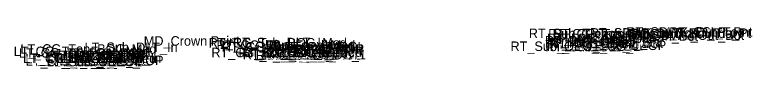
# Model space of a CAD drawing. Extents: x 0 to 6300, y 0 to 9528.
# Drawn here: x 2126 to 2203.7, y 9500.5 to 9504.9 of the extents above; entities that cross this region are included whole.
import ezdxf

# ---------------------------------------------------------------- set-up
doc = ezdxf.new("R2010")
doc.units = 0
doc.layers.add('Default', color=7, linetype='Continuous')

msp = doc.modelspace()

# ---------------------------------------------------------------- texts
at = {"layer": 'Default'}
for s, p in [('RT_Sub_Trench_Out_DLT', (2180.181, 9503.749)), ('RT_CG_Top_Face', (2182.225, 9503.709)), ('RT_CG_Top_BOC', (2182.694, 9503.709)), ('RT_SDWK_In_Top', (2186.62, 9503.799)), ('RT_SDWK_Out_Top', (2190.462, 9503.899)), ('RT_SDWK_Out_Bot', (2190.711, 9503.566)), ('Exterior Boundary', (2192.061, 9503.779)), ('RT_CSLP_Pnt', (2194.981, 9503.899)), ('RT_Tie_Pt', (2197.224, 9503.779)), ('MD_Crown Point', (2139.582, 9502.953)), ('RT_CG_Top_BOC_Med', (2146.431, 9502.753)), ('RT_Sub_DLT_In', (2148.978, 9502.795)), ('RT_PV2_OEOT', (2181.873, 9502.979)), ('RT_PV3_OEOT', (2181.873, 9502.729)), ('RT_PV1_OEOT', (2182.112, 9503.229)), ('RT_CG1_Shelf_Out', (2182.36, 9502.736)), ('RT_CG_Top_Gut', (2182.752, 9503.209)), ('RT_SDWK_In_Bot', (2186.869, 9503.466)), ('LT_CG_Top_BOC_Med', (2126.569, 9502.108)), ('LT_Sub_DLT_In', (2133.339, 9502.288)), ('RT_CG_Top_Face_Med', (2147.246, 9502.503)), ('RT_CG_Top_Gut_Med', (2147.8, 9502.337)), ('RT_PV2_OEEOP', (2152.167, 9502.109)), ('RT_PV2_IEEOP', (2152.928, 9502.109)), ('RT_PV2_PGL', (2154.145, 9502.109)), ('RT_PV1_PGL', (2154.385, 9502.359)), ('RT_Sub_OEOT_CG_1', (2178.247, 9502.396)), ('RT_Sub_OEOT', (2181.92, 9502.354)), ('RT_CG_Bot_IE', (2182.221, 9502.646)), ('RT_CG_Bot_BOC', (2182.97, 9502.721)), ('RT_Sub_OEOP', (2185.154, 9502.493)), ('LT_CG_Top_Face_Med', (2125.866, 9501.858)), ('LT_CG_Top_Gut_Med', (2126.418, 9501.692)), ('LT_CG_Bot_BOC_Med', (2126.846, 9501.131)), ('LT_PV2_OEEOP', (2129.285, 9501.419)), ('LT_PV3_OEEOP', (2129.285, 9501.169)), ('LT_PV2_IEEOP', (2130.046, 9501.419)), ('LT_CG1_Shelf_In', (2130.712, 9501.146)), ('LT_PV2_PGL', (2131.264, 9501.419)), ('LT_PV1_PGL', (2131.503, 9501.669)), ('RT_CG_Bot_BOC_Med', (2146.708, 9501.731)), ('RT_CG1_Shelf_In', (2149.573, 9501.716)), ('RT_CG_Bot_IE_Med', (2149.976, 9501.776)), ('RT_Sub_IEOT_CG_1', (2150.007, 9501.526)), ('RT_Sub_IEOP', (2151.404, 9501.458)), ('RT_PV3_OEEOP', (2152.167, 9501.859)), ('RT_Sub_OEEOP', (2152.214, 9501.484)), ('RT_Sub_IEEOP', (2152.975, 9501.484)), ('RT_Sub_PGL', (2154.192, 9501.484)), ('LT_CG_Bot_IE_Med', (2127.094, 9501.086)), ('LT_Sub_IEOT_CG_1', (2127.125, 9500.836)), ('LT_Sub_OEEOP', (2129.332, 9500.794)), ('LT_Sub_IEEOP', (2130.093, 9500.794)), ('LT_Sub_PGL', (2131.311, 9500.794)), ('LT_Sub_IEOP', (2133.043, 9500.903))]:
    msp.add_text(s, height=1, dxfattribs=at).set_placement(p)

doc.saveas('drawing.dxf')
